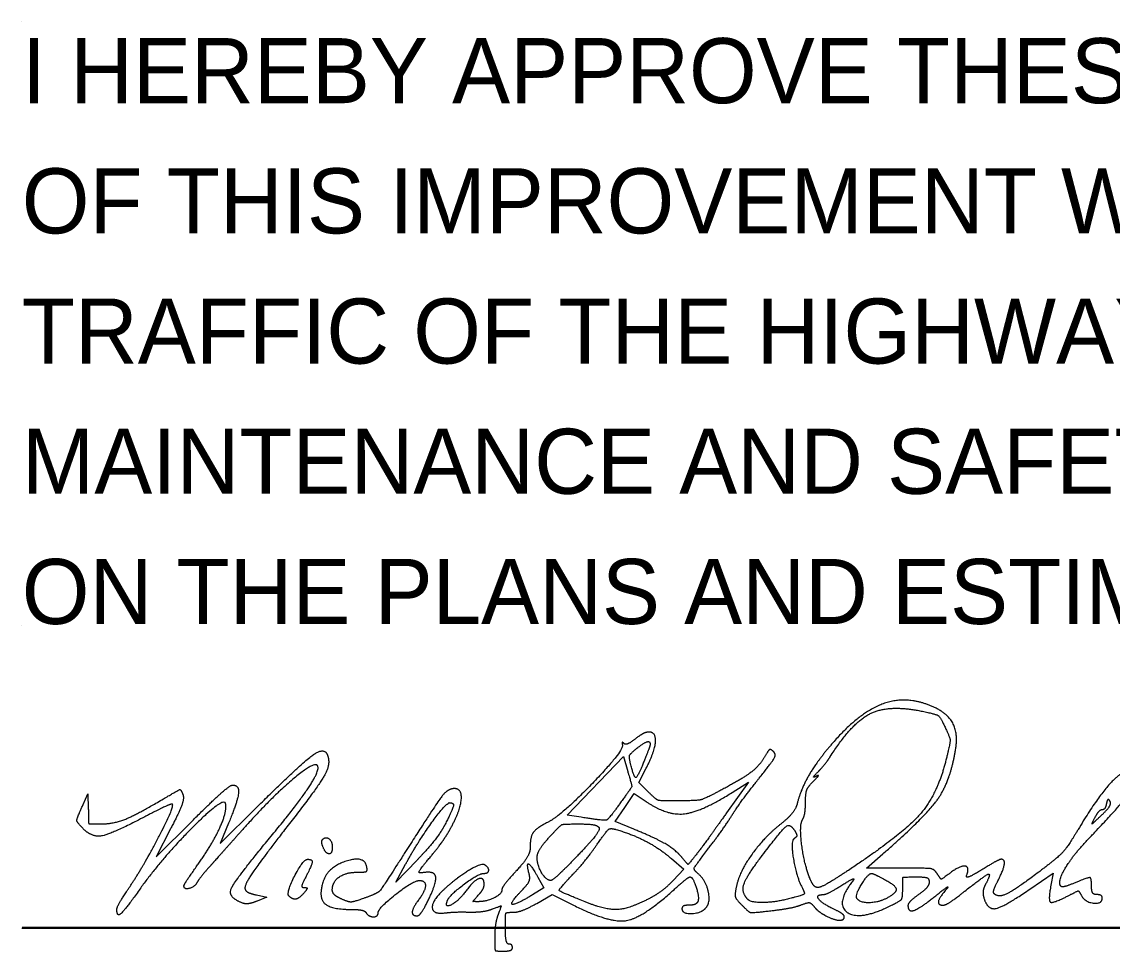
# Model space of a CAD drawing. Extents: x 0 to 82.7, y -0.2 to 22.
# Drawn here: x 24.528 to 26.874, y 8.876 to 10.875 of the extents above; entities that cross this region are included whole.
import ezdxf

# ---------------------------------------------------------------- set-up
doc = ezdxf.new("R2010")
doc.units = 0
for name, color, linetype in [('Default', 7, 'Continuous'), ('SH_Data', 7, 'Continuous'), ('SH_Text', 7, 'Continuous')]:
    doc.layers.add(name, color=color, linetype=linetype)

msp = doc.modelspace()

# ---------------------------------------------------------------- linework, layer by layer
at = {"layer": 'SH_Data'}
for p, q in [((24.5279, 10.875), (24.5279, 10.875)), ((24.5279, 9.5762), (24.5279, 9.5762)), ((24.5279, 9.5762), (24.5279, 9.5762)), ((24.5279, 8.9262), (28.0279, 8.9262)), ((24.5285, 8.928), (28.0285, 8.928))]:
    msp.add_line(p, q, dxfattribs=at)
at = {"layer": 'SH_Text'}
for p, q in [((26.8696, 9.199), (26.8696, 9.199)), ((25.1758, 9.101), (25.1758, 9.101)), ((25.1026, 8.9952), (25.1026, 8.9952)), ((24.7324, 8.9669), (24.7324, 8.9669))]:
    msp.add_line(p, q, dxfattribs=at)
for points in [[(25.7318, 9.1644), (25.7014, 9.1692), (25.8223, 9.2949), (25.8318, 9.2628)], [(25.8757, 9.2193), (25.8558, 9.2392), (25.8717, 9.2703)], [(26.0562, 9.2177), (26.0913, 9.24), (26.0445, 9.1739)], [(24.6599, 9.1919), (24.6703, 9.2147), (24.671, 9.1824)], [(25.8451, 9.1386), (25.8049, 9.155), (25.8253, 9.1854), (25.8458, 9.2157), (25.8716, 9.1981)], [(24.9728, 9.1518), (24.9548, 9.1083), (25.0318, 9.1843)], [(24.8482, 9.1398), (24.817, 9.0792), (24.8945, 9.1564)], [(26.418, 9.0551), (26.3458, 9.0551), (26.3806, 9.0855)], [(25.3783, 9.0722), (25.3329, 9.0247), (25.3538, 9.0633)], [(25.9256, 9.0756), (25.9522, 9.0526), (25.9294, 9.0285)], [(25.6385, 9.0358), (25.6515, 9.0128), (25.6271, 8.9978)], [(26.6969, 9.0097), (26.7471, 9.0441), (26.7423, 9.0181)], [(25.0332, 8.9974), (25.0554, 8.9929), (25.0345, 8.9843)], [(25.6358, 8.9793), (25.6691, 8.9983), (25.715, 8.9754)]]:
    msp.add_lwpolyline(points, dxfattribs=at)
for points in [[(26.4956, 9.3987), (26.4387, 9.4271), (26.3334, 9.393), (26.2757, 9.3275)], [(26.2676, 9.2951), (26.3146, 9.3687), (26.3952, 9.4075), (26.4686, 9.3918)], [(26.4686, 9.3918), (26.4961, 9.3859), (26.5041, 9.3801), (26.5146, 9.358)], [(26.5373, 9.3097), (26.5427, 9.3425), (26.5227, 9.3852), (26.4956, 9.3987)], [(25.8772, 9.3477), (25.8715, 9.3477), (25.8583, 9.3409), (25.8478, 9.3327)], [(25.8717, 9.2703), (25.89, 9.3061), (25.8929, 9.3477), (25.8772, 9.3477)], [(26.5146, 9.358), (26.5253, 9.3353), (26.5259, 9.3258), (26.5182, 9.2939)], [(25.8204, 9.3204), (25.8241, 9.3087), (25.691, 9.1698), (25.6617, 9.1548)], [(25.8234, 9.3232), (25.8204, 9.3262), (25.819, 9.325), (25.8204, 9.3204)], [(25.8478, 9.3327), (25.8374, 9.3245), (25.8264, 9.3202), (25.8234, 9.3232)], [(25.8498, 9.3114), (25.8658, 9.3243), (25.88, 9.3289), (25.88, 9.3212)], [(25.88, 9.3212), (25.88, 9.3192), (25.8745, 9.3038), (25.8677, 9.287)], [(26.2757, 9.3275), (26.2421, 9.2893), (26.2042, 9.2255), (26.1966, 9.1944)], [(25.0318, 9.1843), (25.1262, 9.2775), (25.1786, 9.3164), (25.1856, 9.2984)], [(25.1856, 9.2984), (25.1925, 9.2804), (25.1705, 9.2371), (25.1237, 9.1767)], [(25.8384, 9.2772), (25.8344, 9.2933), (25.8369, 9.301), (25.8498, 9.3114)], [(26.1299, 9.3001), (26.1168, 9.2768), (26.0835, 9.2501), (26.0361, 9.2246)], [(26.1146, 9.2485), (26.1426, 9.2832), (26.1515, 9.2996), (26.1456, 9.3054)], [(26.1456, 9.3054), (26.1398, 9.3111), (26.1352, 9.3096), (26.1299, 9.3001)], [(26.241, 9.2619), (26.2493, 9.2703), (26.2613, 9.2852), (26.2676, 9.2951)], [(26.5182, 9.2939), (26.4994, 9.2153), (26.4229, 9.1273), (26.3065, 9.0503)], [(26.3806, 9.0855), (26.4728, 9.1661), (26.5262, 9.2425), (26.5373, 9.3097)], [(25.1636, 9.2762), (25.1558, 9.2839), (25.0648, 9.2069), (25.0124, 9.1482)], [(25.0705, 9.1311), (25.1246, 9.1965), (25.171, 9.2688), (25.1636, 9.2762)], [(25.8677, 9.287), (25.8534, 9.2512), (25.8456, 9.2486), (25.8384, 9.2772)], [(25.8318, 9.2628), (25.8409, 9.2318), (25.8404, 9.2294), (25.8164, 9.1961)], [(26.0564, 9.1692), (26.0669, 9.1859), (26.0931, 9.2216), (26.1146, 9.2485)], [(26.2315, 9.2421), (26.2409, 9.2512), (26.2434, 9.256), (26.2372, 9.2527)], [(26.2372, 9.2527), (26.2309, 9.2493), (26.2326, 9.2535), (26.241, 9.2619)], [(26.9136, 9.235), (26.9136, 9.2763), (26.8519, 9.2233), (26.8009, 9.1381)], [(24.8325, 9.204), (24.8655, 9.2235), (24.8702, 9.2245), (24.8746, 9.2132)], [(24.8945, 9.1564), (24.9372, 9.1989), (24.9762, 9.2337), (24.9814, 9.2337)], [(24.9814, 9.2337), (24.9961, 9.2337), (24.9925, 9.1994), (24.9728, 9.1518)], [(25.4586, 9.2261), (25.4446, 9.2261), (25.4187, 9.1925), (25.351, 9.0864)], [(25.4536, 9.1462), (25.4724, 9.1818), (25.4751, 9.2261), (25.4586, 9.2261)], [(26.0361, 9.2246), (25.9987, 9.2045), (25.9814, 9.1999), (25.9429, 9.1997)], [(26.2143, 9.1973), (26.2143, 9.2164), (26.2199, 9.2308), (26.2315, 9.2421)], [(26.8214, 9.1159), (26.8807, 9.1779), (26.9136, 9.2203), (26.9136, 9.235)], [(24.6972, 9.1501), (24.7251, 9.1501), (24.7741, 9.1696), (24.8325, 9.204)], [(24.8746, 9.2132), (24.8775, 9.2055), (24.8672, 9.1766), (24.8482, 9.1398)], [(25.8716, 9.1981), (25.9158, 9.1679), (25.9901, 9.1758), (26.0562, 9.2177)], [(25.9429, 9.1997), (25.9018, 9.1995), (25.8929, 9.2021), (25.8757, 9.2193)], [(26.8511, 9.1687), (26.8641, 9.1809), (26.8724, 9.1946), (26.8696, 9.199)], [(26.8696, 9.199), (26.8666, 9.2038), (26.8635, 9.2016), (26.8619, 9.1938)], [(24.6615, 9.1384), (24.6463, 9.1536), (24.6461, 9.1617), (24.6599, 9.1919)], [(24.671, 9.1824), (24.6716, 9.1509), (24.6722, 9.1501), (24.6972, 9.1501)], [(24.7598, 9.0144), (24.7896, 9.0586), (24.8567, 9.1879), (24.8521, 9.1924)], [(24.9665, 9.1936), (24.9633, 9.2104), (24.8296, 9.077), (24.7802, 9.0076)], [(24.8521, 9.1924), (24.8506, 9.194), (24.8237, 9.1818), (24.7924, 9.1654)], [(24.9033, 9.0577), (24.9361, 9.1035), (24.9699, 9.1761), (24.9665, 9.1936)], [(25.1237, 9.1767), (25.046, 9.0763), (25.0057, 9.018), (25.0083, 9.0099)], [(25.3538, 9.0633), (25.3782, 9.1087), (25.4405, 9.1955), (25.4487, 9.1956)], [(25.4487, 9.1956), (25.4582, 9.1957), (25.4552, 9.1814), (25.4391, 9.1498)], [(25.8164, 9.1961), (25.7905, 9.1598), (25.7815, 9.1565), (25.7318, 9.1644)], [(26.1966, 9.1944), (26.1938, 9.1833), (26.1778, 9.1632), (26.1609, 9.1498)], [(26.2079, 9.1593), (26.2113, 9.1647), (26.2142, 9.1818), (26.2143, 9.1973)], [(26.8525, 9.1805), (26.8488, 9.1805), (26.8416, 9.1728), (26.8366, 9.1635)], [(26.8619, 9.1938), (26.8604, 9.1864), (26.8562, 9.1805), (26.8525, 9.1805)], [(24.7924, 9.1654), (24.7231, 9.1291), (24.6798, 9.1202), (24.6615, 9.1384)], [(25.6617, 9.1548), (25.635, 9.1412), (25.6216, 9.1219), (25.6216, 9.0972)], [(26.0445, 9.1739), (26.0188, 9.1376), (25.9904, 9.0986), (25.9815, 9.0872)], [(26.0044, 9.0958), (26.0224, 9.1194), (26.0458, 9.1524), (26.0564, 9.1692)], [(26.2233, 9.0342), (26.211, 9.0657), (26.2009, 9.1481), (26.2079, 9.1593)], [(26.8366, 9.1635), (26.829, 9.1493), (26.8315, 9.1502), (26.8511, 9.1687)], [(25.0124, 9.1482), (24.9817, 9.1138), (24.9463, 9.0743), (24.9338, 9.0602)], [(25.0028, 8.9799), (24.9701, 8.9924), (24.9872, 9.0305), (25.0705, 9.1311)], [(25.4391, 9.1498), (25.4306, 9.1333), (25.4033, 9.0984), (25.3783, 9.0722)], [(25.4071, 9.0792), (25.4239, 9.0994), (25.4448, 9.1295), (25.4536, 9.1462)], [(25.663, 9.1216), (25.6866, 9.1472), (25.693, 9.1501), (25.7271, 9.1501)], [(25.7699, 9.1423), (25.7725, 9.138), (25.7516, 9.1107), (25.7235, 9.0815)], [(25.7271, 9.1501), (25.748, 9.1501), (25.7672, 9.1466), (25.7699, 9.1423)], [(25.7661, 9.1064), (25.7863, 9.1353), (25.7947, 9.1417), (25.8072, 9.138)], [(25.8072, 9.138), (25.843, 9.1275), (25.9007, 9.0971), (25.9256, 9.0756)], [(25.9484, 9.0778), (25.9348, 9.0942), (25.8913, 9.1199), (25.8451, 9.1386)], [(26.1609, 9.1498), (26.1247, 9.1212), (26.0715, 9.0459), (26.0652, 9.0142)], [(26.1213, 9.0825), (26.1639, 9.1385), (26.1812, 9.1514), (26.1914, 9.1351)], [(26.1914, 9.1351), (26.1958, 9.128), (26.1954, 9.1221), (26.1904, 9.119)], [(26.8009, 9.1381), (26.7784, 9.1006), (26.7566, 9.077), (26.7162, 9.0466)], [(25.1758, 9.101), (25.1733, 9.1074), (25.1732, 9.1146), (25.1755, 9.117)], [(25.1755, 9.117), (25.1822, 9.1236), (25.196, 9.1123), (25.196, 9.1002)], [(25.6368, 9.0777), (25.6368, 9.0861), (25.6486, 9.1059), (25.663, 9.1216)], [(25.7139, 9.0418), (25.7287, 9.0574), (25.7522, 9.0865), (25.7661, 9.1064)], [(26.1904, 9.119), (26.182, 9.1138), (26.1944, 9.0369), (26.2077, 9.0117)], [(26.7641, 9.0158), (26.7557, 9.0242), (26.7883, 9.0813), (26.8214, 9.1159)], [(25.196, 9.1002), (25.196, 9.0856), (25.1815, 9.0862), (25.1758, 9.101)], [(25.351, 9.0864), (25.3034, 9.0118), (25.2934, 9.0006), (25.2661, 8.9909)], [(25.6216, 9.0972), (25.6216, 9.0885), (25.6079, 9.0665), (25.5912, 9.0483)], [(25.7235, 9.0815), (25.6953, 9.0523), (25.6696, 9.0285), (25.6664, 9.0285)], [(25.9815, 9.0872), (25.9626, 9.0631), (25.961, 9.0627), (25.9484, 9.0778)], [(25.9826, 9.0436), (25.9731, 9.0515), (25.9763, 9.0592), (26.0044, 9.0958)], [(26.0902, 8.9879), (26.0758, 9.0024), (26.0876, 9.0383), (26.1213, 9.0825)], [(24.8768, 9.017), (24.8768, 9.0191), (24.8887, 9.0374), (24.9033, 9.0577)], [(24.9338, 9.0602), (24.9212, 9.0462), (24.9082, 9.0299), (24.9049, 9.024)], [(25.1026, 8.9952), (25.0963, 9.0015), (25.1334, 9.0741), (25.1429, 9.0741)], [(25.1429, 9.0741), (25.1535, 9.0741), (25.1522, 9.0616), (25.1388, 9.0357)], [(25.2701, 9.0582), (25.265, 9.0832), (25.1859, 9.0566), (25.1764, 9.0268)], [(25.2496, 9.0462), (25.2666, 9.0462), (25.2719, 9.0494), (25.2701, 9.0582)], [(25.3898, 9.045), (25.3806, 9.0433), (25.3859, 9.0538), (25.4071, 9.0792)], [(25.5239, 9.062), (25.5165, 9.0665), (25.4594, 9.0313), (25.433, 9.0059)], [(25.5216, 9.0437), (25.5318, 9.0437), (25.5334, 9.0561), (25.5239, 9.062)], [(25.6195, 9.0432), (25.6135, 9.0661), (25.6234, 9.0622), (25.6385, 9.0358)], [(25.6664, 9.0285), (25.6565, 9.0285), (25.6368, 9.0612), (25.6368, 9.0777)], [(26.561, 9.0394), (26.568, 9.0577), (26.548, 9.0611), (26.5266, 9.0453)], [(26.6351, 9.0741), (26.6324, 9.0741), (26.6138, 9.0639), (26.5937, 9.0515)], [(26.628, 9.0274), (26.6403, 9.0511), (26.6438, 9.0741), (26.6351, 9.0741)], [(25.1388, 9.0357), (25.1309, 9.0205), (25.13, 9.0133), (25.1359, 9.0133)], [(25.196, 9.0081), (25.196, 9.0255), (25.2252, 9.0462), (25.2496, 9.0462)], [(25.4029, 8.987), (25.4212, 9.0246), (25.4155, 9.0498), (25.3898, 9.045)], [(25.4439, 8.9856), (25.4487, 8.9974), (25.5107, 9.0437), (25.5216, 9.0437)], [(25.5912, 9.0483), (25.5744, 9.0302), (25.5608, 9.012), (25.5608, 9.0079)], [(25.6021, 9.0052), (25.6166, 9.0203), (25.6222, 9.0327), (25.6195, 9.0432)], [(25.74, 8.9825), (25.6848, 9.0047), (25.6829, 9.009), (25.7139, 9.0418)], [(25.9313, 9.0087), (25.948, 9.0238), (25.9634, 9.0361), (25.9656, 9.0361)], [(25.9656, 9.0361), (25.9723, 9.0361), (25.9865, 8.9892), (25.982, 8.982)], [(26.0004, 8.9701), (26.0106, 8.9824), (25.9991, 9.03), (25.9826, 9.0436)], [(26.2409, 9.0133), (26.2357, 9.0133), (26.2277, 9.0227), (26.2233, 9.0342)], [(26.3065, 9.0503), (26.2757, 9.0299), (26.2461, 9.0133), (26.2409, 9.0133)], [(26.3247, 8.9903), (26.3207, 8.9967), (26.349, 9.0437), (26.3568, 9.0437)], [(26.3568, 9.0437), (26.3583, 9.0437), (26.3696, 9.0384), (26.3819, 9.0321)], [(26.498, 9.0425), (26.4916, 9.0527), (26.4767, 9.0551), (26.418, 9.0551)], [(26.4234, 9.0096), (26.4234, 9.0348), (26.425, 9.0361), (26.4576, 9.0361)], [(26.4576, 9.0361), (26.4723, 9.0361), (26.4804, 9.0322), (26.4804, 9.0252)], [(26.5266, 9.0453), (26.5077, 9.0313), (26.5052, 9.0311), (26.498, 9.0425)], [(26.5573, 9.0057), (26.5999, 9.0394), (26.6145, 9.0442), (26.6018, 9.0206)], [(26.5937, 9.0515), (26.5735, 9.0392), (26.5589, 9.0337), (26.561, 9.0394)], [(26.7162, 9.0466), (26.6653, 9.0083), (26.6293, 8.991), (26.6201, 9.0002)], [(26.83, 9.012), (26.83, 9.0335), (26.8233, 9.0357), (26.7943, 9.0236)], [(24.7324, 8.9669), (24.7324, 8.9707), (24.7447, 8.992), (24.7598, 9.0144)], [(24.9049, 9.024), (24.8993, 9.0141), (24.8768, 9.0085), (24.8768, 9.017)], [(25.0083, 9.0099), (25.0098, 9.0055), (25.021, 8.9998), (25.0332, 8.9974)], [(25.1359, 9.0133), (25.1421, 9.0133), (25.1419, 9.01), (25.1352, 9.0019)], [(25.1764, 9.0268), (25.1656, 8.9927), (25.1928, 8.9661), (25.2387, 8.9661)], [(25.2948, 8.9594), (25.2948, 8.9692), (25.3706, 9.0285), (25.3832, 9.0285)], [(25.3832, 9.0285), (25.3967, 9.0285), (25.3961, 9.0058), (25.3819, 8.9871)], [(25.5228, 9.0196), (25.5228, 9.0362), (25.5005, 9.0286), (25.484, 9.0063)], [(25.5102, 8.9968), (25.5171, 9.0044), (25.5228, 9.0147), (25.5228, 9.0196)], [(25.9294, 9.0285), (25.9168, 9.0152), (25.8935, 8.9976), (25.8775, 8.9893)], [(26.0652, 9.0142), (26.0619, 8.9975), (26.065, 8.9879), (26.0777, 8.9752)], [(26.2077, 9.0117), (26.2133, 9.0011), (26.2095, 8.9974), (26.1859, 8.9909)], [(26.2519, 8.9981), (26.2565, 8.9981), (26.2747, 9.0072), (26.2924, 9.0183)], [(26.2924, 9.0183), (26.3101, 9.0294), (26.3208, 9.0337), (26.3162, 9.0278)], [(26.3162, 9.0278), (26.2775, 8.9777), (26.3313, 8.9417), (26.3968, 8.9739)], [(26.3819, 9.0321), (26.4078, 9.0187), (26.4109, 9.0021), (26.3897, 8.9907)], [(26.4804, 9.0252), (26.4804, 9.0192), (26.4701, 9.007), (26.4576, 8.9981)], [(26.4948, 8.9958), (26.514, 9.0113), (26.5238, 9.017), (26.5165, 9.0085)], [(26.6018, 9.0206), (26.5973, 9.0121), (26.5957, 8.9984), (26.5983, 8.9902)], [(26.6201, 9.0002), (26.6179, 9.0024), (26.6214, 9.0147), (26.628, 9.0274)], [(26.7423, 9.0181), (26.7361, 8.9854), (26.7464, 8.9786), (26.7777, 8.9947)], [(26.7943, 9.0236), (26.7796, 9.0174), (26.766, 9.0139), (26.7641, 9.0158)], [(26.8414, 8.9981), (26.8351, 8.9981), (26.83, 9.0043), (26.83, 9.012)], [(24.7802, 9.0076), (24.7489, 8.9638), (24.7324, 8.9497), (24.7324, 8.9669)], [(25.1352, 9.0019), (25.1253, 8.99), (25.1107, 8.987), (25.1026, 8.9952)], [(25.2155, 8.9888), (25.2048, 8.9937), (25.196, 9.0024), (25.196, 9.0081)], [(25.2661, 8.9909), (25.2416, 8.9822), (25.231, 8.9818), (25.2155, 8.9888)], [(25.3819, 8.9871), (25.369, 8.9701), (25.3673, 8.9525), (25.3785, 8.9525)], [(25.3785, 8.9525), (25.3827, 8.9525), (25.3937, 8.968), (25.4029, 8.987)], [(25.433, 9.0059), (25.4094, 8.9832), (25.413, 8.9553), (25.4392, 8.9588)], [(25.484, 9.0063), (25.4679, 8.9844), (25.4368, 8.9684), (25.4439, 8.9856)], [(25.5098, 8.9829), (25.4987, 8.9829), (25.4988, 8.9841), (25.5102, 8.9968)], [(25.5608, 9.0079), (25.5608, 8.9992), (25.5275, 8.9829), (25.5098, 8.9829)], [(25.6271, 8.9978), (25.5899, 8.9752), (25.577, 8.979), (25.6021, 9.0052)], [(25.715, 8.9754), (25.7925, 8.9366), (25.8637, 8.9476), (25.9313, 9.0087)], [(25.8775, 8.9893), (25.8343, 8.9671), (25.7845, 8.9646), (25.74, 8.9825)], [(26.1859, 8.9909), (26.1538, 8.982), (26.0979, 8.9802), (26.0902, 8.9879)], [(26.2735, 8.9677), (26.2495, 8.979), (26.2359, 8.9981), (26.2519, 8.9981)], [(26.3897, 8.9907), (26.3711, 8.9808), (26.3307, 8.9805), (26.3247, 8.9903)], [(26.3968, 8.9739), (26.4183, 8.9845), (26.4234, 8.9913), (26.4234, 9.0096)], [(26.4576, 8.9981), (26.445, 8.9891), (26.4348, 8.9786), (26.4348, 8.9747)], [(26.4348, 8.9747), (26.4348, 8.9596), (26.4614, 8.9689), (26.4948, 8.9958)], [(26.5165, 9.0085), (26.5017, 8.9913), (26.499, 8.9753), (26.511, 8.9753)], [(26.511, 8.9753), (26.5153, 8.9753), (26.5361, 8.9889), (26.5573, 9.0057)], [(26.5983, 8.9902), (26.6063, 8.9648), (26.6415, 8.9717), (26.6969, 9.0097)], [(26.7777, 8.9947), (26.7998, 9.0062), (26.8025, 9.0062), (26.8087, 8.9951)], [(26.8087, 8.9951), (26.8161, 8.9818), (26.8528, 8.978), (26.8528, 8.9905)], [(26.8528, 8.9905), (26.8528, 8.9946), (26.8476, 8.9981), (26.8414, 8.9981)], [(25.0345, 8.9843), (25.0231, 8.9796), (25.0088, 8.9776), (25.0028, 8.9799)], [(25.2387, 8.9661), (25.2528, 8.9661), (25.2663, 8.9631), (25.2686, 8.9593)], [(25.4899, 8.9606), (25.5073, 8.9603), (25.5303, 8.9633), (25.5409, 8.9673)], [(25.5409, 8.9673), (25.5592, 8.9743), (25.5598, 8.9737), (25.5529, 8.9555)], [(25.5855, 8.9602), (25.5949, 8.9602), (25.6175, 8.9688), (25.6358, 8.9793)], [(25.9631, 8.9753), (25.955, 8.9753), (25.9484, 8.9718), (25.9484, 8.9677)], [(25.9484, 8.9677), (25.9484, 8.9565), (25.9907, 8.9584), (26.0004, 8.9701)], [(25.982, 8.982), (25.9797, 8.9783), (25.9712, 8.9753), (25.9631, 8.9753)], [(26.0777, 8.9752), (26.0927, 8.9601), (26.0994, 8.9588), (26.14, 8.9634)], [(26.14, 8.9634), (26.1649, 8.9663), (26.194, 8.9719), (26.2046, 8.9759)], [(26.2046, 8.9759), (26.2189, 8.9813), (26.226, 8.9805), (26.2324, 8.9726)], [(26.2324, 8.9726), (26.2371, 8.9667), (26.2478, 8.9582), (26.2562, 8.9536)], [(26.2978, 8.9506), (26.2977, 8.9537), (26.2868, 8.9614), (26.2735, 8.9677)], [(25.2686, 8.9593), (25.2742, 8.9504), (25.2948, 8.9504), (25.2948, 8.9594)], [(25.4392, 8.9588), (25.4496, 8.9601), (25.4724, 8.961), (25.4899, 8.9606)], [(25.5529, 8.9555), (25.5489, 8.9449), (25.5456, 8.9228), (25.5456, 8.9064)], [(25.5684, 8.9259), (25.5684, 8.9562), (25.5703, 8.9601), (25.5855, 8.9602)], [(26.2562, 8.9536), (26.2737, 8.944), (26.298, 8.9422), (26.2978, 8.9506)], [(25.576, 8.8917), (25.5718, 8.8917), (25.5684, 8.9071), (25.5684, 8.9259)], [(25.5456, 8.9064), (25.5456, 8.8795), (25.5475, 8.8765), (25.5646, 8.8765)], [(25.5646, 8.8765), (25.575, 8.8765), (25.5836, 8.8799), (25.5836, 8.8841)], [(25.5836, 8.8841), (25.5836, 8.8882), (25.5801, 8.8917), (25.576, 8.8917)]]:
    msp.add_open_spline(points, degree=2, dxfattribs=at)

# ---------------------------------------------------------------- texts
at = {"layer": 'Default'}
for s, p in [('I HEREBY APPROVE THESE PLANS AND DECLARE THAT THE MAKING', (24.5279, 10.7)), ('OF THIS IMPROVEMENT WILL NOT REQUIRE THE CLOSING TO', (24.5279, 10.42)), ('TRAFFIC OF THE HIGHWAY AND THAT PROVISIONS FOR THE', (24.5279, 10.14)), ('MAINTENANCE AND SAFETY OF TRAFFIC WILL BE AS SET FORTH', (24.5279, 9.86)), ('ON THE PLANS AND ESTIMATES.', (24.5279, 9.58))]:
    msp.add_text(s, height=0.14, dxfattribs=at).set_placement(p)

doc.saveas('drawing.dxf')
